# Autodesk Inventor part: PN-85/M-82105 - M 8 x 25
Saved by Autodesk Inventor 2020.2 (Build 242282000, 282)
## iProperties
Manager: www.cadconsulting.pl
Company: Fabian Stasiak CAD Consulting
Created: 2005-10
Part Number: PN-85/M-82105 - M 8 x 25
Material: Stal, miękka
Description: Śruba - A
Vendor: Autodesk Inc.
Document SubType Name: Modeling
Standard: PN-85/M-82105
Designer: F.Stasiak
Standards Organization: PN
Language: pl-PL
Size Designation: M 8 x 25
Categories: <MemberInstance Version="R10.0.0"><Categories><Category DisplayName="Mocowania" InternalName="e4da775c-781d-43d5-af7c-5136215cf5a6" Mnemonic="FSTN"><Category Di
Density: 1 g/cm^3
Appearance: Stal
Author: F.Stasiak
Subject: Zbiór ćwiczeń. Autodesk Inventor 2020. Kurs podstawowy
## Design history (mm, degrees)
sketch "Szkic1"
  geometry: L1 (0, 5.8)-(0, 4); L2 (4, 4)-(25, 4); L3 (25, 4)-(25, 0); L4 (25, 0)-(-0.6, 0); L5 (-3.16, 0)-(32.68, 0) reference; L6 (-0.6, 0)-(-0.6, 5.8); L7 (-0.6, 5.8)-(0, 5.8); L8 (4, 4)-(3.233, 4); L9 (3.233, 4)-(0, 4); L10 (0, -0.58)-(0, 7.54) reference
  constraints: 16 end point, 2 collinear, 2 perpendicular, 1 parallel
  dimensions: "d0" = 25 distance between parallel lines of L3 L1 (= NLG); "d1" = 21 distance from line of L2.start L3 (= GEL); "d2" = 8 diameter of L2 L4 (= GD); "d9" = 0.6001 distance between parallel lines of L6 L1 (computed from SD); "d10" = 11.6 diameter of L7 L4 (= SD2); "d13" = 0.76691 distance of L2.start L8.end (computed from GAL); "d14" = 8 diameter of L9 L4 (= BDM)
revolve "Bryła" sketch "Szkic1" stored, may be unused: angle "d12" = 90 deg
sketch "Szkic2"
  geometry: L1 (0, 7.506)-(6.5, 3.753); L2 (6.5, 3.753)-(6.5, -3.753); L3 (6.5, -3.753)-(0, -7.506); L4 (0, -7.506)-(-6.5, -3.753); L5 (-6.5, -3.753)-(-6.5, 3.753); L6 (-6.5, 3.753)-(0, 7.506); 2 further points
  constraints: 12 end point, 1 coincident, 1 vertical, 11 other
  dimensions: "d11" = 13 distance between parallel lines of L5 L2 (= SW)
extrude "Głowica" join sketch "Szkic2" distance "d3" = 4.7 (= KOH - SD); taper "d4" = 0 deg
sketch "Szkic4"
  geometry: L1 (-5.3, 6.5)-(-5.3, 7.506); L2 (-5.3, 7.506)-(-4.72, 7.506); L3 (-4.72, 7.506)-(-5.3, 6.5); L4 (-5.77, 0)-(0.81, 0) reference; L5 (-0.6, 7.506)-(-5.3, 7.506) reference; L6 (-5.3, 3.753)-(-5.3, 7.506) reference
  constraints: 6 end point, 2 collinear, 1 perpendicular, 1 vertical
  dimensions: "d5" = 30 deg angle of L3 L1 (= ANG1); "d19" = 13 diameter of L1.start L4 (= SW0)
revolve "Faza1" sketch "Szkic4" stored, may be unused: angle "d21" = 90 deg
node "Bryła1"
node "Korpusy bryłowe"
node "Korpusy powierzchniowe"
feature "Gwint" dims "d15" = 21 (= GEL), "d16" = 0
chamfer "Faza2" distance "d6" = 0.76681 (= -0.5 x SPD + 0.5 x GD); stored, may be unused: second distance "d7" = 0.76691 (computed from GUL), angle "d55" = 45 deg
other parameters: "NLG" = 25 [user parameter; used in 2 equation terms], "GD" = 8 (= NND) [user parameter; used in 2 equation terms], "BDM" = 8 (= NND) [user parameter; used in 1 equation term], "KOH" = 5.3 [user parameter; used in 1 equation term], "GEL" = 21 [user parameter; used in 2 equation terms], "SW" = 13 [user parameter; used in 3 equation terms], "SW0" = 13 (= SW) [user parameter; used in 1 equation term], "SPD" = 6.46637 (= NND - 1.2269 x PTC) [user parameter; used in 1 equation term], "SD2" = 11.6 (= SDH) [user parameter; used in 1 equation term], "SD" = 0.6 [user parameter; used in 3 equation terms], "ANG1" = 30 deg [user parameter; used in 1 equation term], "GAL" = 0.76681 (= 0.61345 x PTC) [user parameter; used in 2 equation terms], "GUL" = 0.76681 (= 0.61345 x PTC) [user parameter; used in 1 equation term], "d8" = 0, "RR" = 0.4 [user parameter], "d56" = -25 (= -NLG), "NND" = 8 [user parameter; used in 3 equation terms], "SDH" = 11.6 [user parameter; used in 1 equation term], "E0" = 15.015 (= 1.155 x SW) [user parameter], "WFT" = 0.6 (= SD) [user parameter], "SDHG" = 0.76681 (= GAL) [user parameter], "FAWI" = 45 deg [user parameter], "THREADDIA" = 8 [user parameter; used in 1 equation term], "TPU" = 8 (computed from PTC) [user parameter], "GD1" = 6.46637 (= THREADDIA - 1.2269 x PTC) [user parameter], "PTC" = 1.25 [user parameter; used in 5 equation terms], "TOA" = 30 deg [user parameter]
